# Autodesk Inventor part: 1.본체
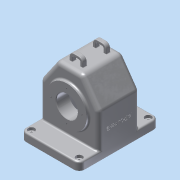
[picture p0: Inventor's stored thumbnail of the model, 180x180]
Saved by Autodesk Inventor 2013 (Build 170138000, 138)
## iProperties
Created: 2016-12
Part Number: 1.본체
Material: 알루미늄 6061
Document SubType Name: Modeling
Designer: Administrator
Density: 2.71 g/cm^3
Mass: 1067.35 g
Surface Area: 1137.96 cm^2
Volume: 393.856 cm^3
Author: Administrator
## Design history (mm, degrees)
sketch "스케치1"
  geometry: L1 (-55, 80)-(-55, 0); L2 (-55, 0)-(55, 0); L3 (55, 0)-(55, 80); L4 (55, 80)-(23.491, 125); L5 (23.491, 125)-(-23.491, 125); L6 (-23.491, 125)-(-55, 80); 3 further points
  constraints: 12 end point, 2 midpoint, 2 parallel, 1 coincident, 1 perpendicular, 1 vertical, 1 vertical alignment
  dimensions: "d0" = 110 distance of L1.end L2.end; "d2" = 80 distance of L2.end L3.end; "d3" = 80 distance of L1.start L1.end; "d4" = 125 distance between parallel lines of L2 L5; "d5" = 35 deg angle of L6 L1; "d6" = 35 deg angle of L4 L3 (derived)
extrude "돌출1" new body sketch "스케치1" stored distance "d7" = 77; taper "d8" = 0 deg
feature "쉘1" dims "d9" = 5
sketch "스케치2"
  geometry: L1 (78.424, 33.5)-(0, 33.5) reference; L2 (80, 38.5)-(0, 38.5) reference; L3 (0, -33.5)-(78.424, -33.5) reference; L4 (0, -38.5)-(80, -38.5) reference; L5 (65, 33.5)-(65, -33.5); L6 (120, 33.5)-(78.424, 33.5) reference; L7 (125, 38.5)-(80, 38.5) reference; L8 (65, 33.5)-(65, 19.5); L9 (65, 19.5)-(92, 19.5); L10 (92, 19.5)-(106, 33.5); 1 further point
  constraints: 8 end point, 4 point on line, 2 perpendicular
  dimensions: "d10" = 65 distance from line of L5 point (0, 0); "d12" = 14 distance between parallel lines of L1 L9; "d13" = 54 diameter of L9.end L5; "d14" = 45 deg angle of L10 L9
revolve "회전1" sketch "스케치2" stored, may be unused: angle "d15" = 90 deg
sketch "스케치3"
  geometry: L1 (-55, 0)-(55, 0) reference; C1 r 37.5 at (0, 65); 2 further points
  constraints: 1 centre point, 1 midpoint, 1 vertical alignment
  dimensions: "d16" = 65 distance of point (0, 0) C1.centre; "d17" = 75 diameter of C1
extrude "돌출2" join sketch "스케치3" distance "d18" = 5; taper "d19" = 0 deg
sketch "스케치4"
  geometry: L1 (-55, 0)-(55, 0) reference; C1 r 31 at (0, 65); 2 further points
  constraints: 1 centre point, 1 midpoint, 1 vertical alignment
  dimensions: "d20" = 65 distance of point (0, 0) C1.centre; "d21" = 62 diameter of C1
extrude "돌출3" join sketch "스케치4" distance "d22" = 10; taper "d23" = 0 deg
hole "구멍1" diameter "d26" = 40; stored, may be unused: countersink angle "d30" = 90 deg, drill point angle "d32" = 118 deg; dims "d24" = 10, "d25" = 10, "d27" = 6, "d28" = 4, "d29" = 2, "d31" = 8
sketch "스케치5" dims "d33" = 58
  geometry: C1 r 20 at (0, 0) reference; 3 further points
  constraints: 2 vertical alignment, 1 coincident, 2 other
hole "구멍2" sketch "스케치5" at (0, 29) diameter "d35" = 2.459; stored, may be unused: countersink angle "d39" = 90 deg, drill point angle "d41" = 118 deg; dims "d36" = 6, "d37" = 4, "d38" = 2, "d40" = 8
sketch "스케치6" dims "d45" = 52
  geometry: C1 r 20 at (0, 0) reference; 3 further points
  constraints: 2 vertical alignment, 1 coincident, 2 other
hole "구멍3" sketch "스케치6" at (0, 26) diameter "d47" = 2.459; stored, may be unused: countersink angle "d51" = 90 deg, drill point angle "d53" = 118 deg; dims "d48" = 6, "d49" = 4, "d50" = 2, "d52" = 8
chamfer "모따기1" distance "d57" = 1; stored, may be unused: second distance "d58" = 2, angle "d59" = 45 deg
sketch "스케치7"
  geometry: L1 (110, -77)-(110, 0) reference; L2 (105, -5)-(105, -72) reference; L3 (105, -72)-(5, -72) reference; L4 (5, -72)-(5, -5) reference; L5 (5, -5)-(105, -5) reference; L6 (110, -77)-(110, 0) reference; L7 (0, 0)-(110, 0) reference; L8 (0, -77)-(0, 0) reference; L9 (110, -77)-(0, -77) reference; L10 (0, 36.5)-(110, 36.5); L11 (110, 36.5)-(110, -113.5); L12 (110, -113.5)-(0, -113.5); L13 (0, -113.5)-(0, 36.5); L14 (0, 36.5)-(110, -113.5); 2 further points
  constraints: 10 end point, 2 parallel, 1 coincident, 1 horizontal, 1 midpoint, 1 perpendicular
  dimensions: "d60" = 150 distance of L12.end L10.start; "d62" = 110 distance of L11.end L12.end
extrude "돌출4" join sketch "스케치7" distance "d63" = 15; taper "d64" = 0 deg
fillet "모깎기1" dims "d65" = 10
sketch "스케치8"
  geometry: L1 (10, -36.5)-(100, -36.5) reference; L2 (110, -26.5)-(110, 0) reference; L3 (0, 0)-(110, 0) reference; L4 (0, 0)-(0, -26.5) reference; L5 (0, 103.5)-(0, 77) reference; L6 (110, 77)-(0, 77) reference; L7 (110, 77)-(110, 103.5) reference; L8 (100, 113.5)-(10, 113.5) reference; A1 r 10 centre (10, -26.5) between (0, -26.5) and (10, -36.5) reference; A2 r 10 centre (100, -26.5) between (100, -36.5) and (110, -26.5) reference; A3 r 10 centre (10, 103.5) between (10, 113.5) and (0, 103.5) reference; A4 r 10 centre (100, 103.5) between (110, 103.5) and (100, 113.5) reference; 1 further point
hole "구멍4" sketch "스케치8" at (10, -26.5), (100, -26.5), (100, 103.5), (10, 103.5) diameter "d66" = 5; stored, may be unused: countersink angle "d70" = 90 deg, drill point angle "d72" = 0 deg; dims "d67" = 6, "d68" = 12, "d69" = 5, "d71" = 8
fillet "모깎기2" dims "d73" = 10
fillet "모깎기3" dims "d74" = 8
node "작업 평면1"
sketch "스케치9"
  geometry: L1 (-18.285, 125)-(18.285, 125) reference; L2 (-7.5, 125)-(-7.5, 135); L3 (-7.5, 135)-(7.5, 135); L4 (7.5, 135)-(7.5, 125); L5 (-12.5, 125)-(-12.5, 140); L6 (-12.5, 140)-(12.5, 140); L7 (12.5, 140)-(12.5, 125); L8 (50, 0)-(-50, 0) reference; 3 further points
  constraints: 12 end point, 5 perpendicular, 4 point on line, 2 midpoint, 2 vertical alignment, 1 parallel
  dimensions: "d76" = 25 distance of L5.end L6.end; "d78" = 15 distance of L2.end L3.end; "d79" = 140 distance between parallel lines of L6 L8; "d80" = 5 distance between parallel lines of L3 L6
extrude "돌출5" join sketch "스케치9" distance "d81" = 8; taper "d82" = 0 deg
fillet "모깎기4" dims "d83" = 8
fillet "모깎기5" dims "d84" = 3
fillet "모깎기6" dims "d85" = 1
fillet "모깎기7" dims "d86" = 1
fillet "모깎기8" dims "d87" = 1
fillet "모깎기9" dims "d88" = 3
fillet "모깎기10" dims "d89" = 3
fillet "모깎기11" dims "d90" = 3
fillet "모깎기12" dims "d91" = 3
fillet "모깎기13" dims "d92" = 5
fillet "모깎기14" dims "d93" = 3
sketch "스케치10"
  geometry: L1 (26.5, 76.847)-(26.5, 18) reference; L2 (130, 0)-(0, 0) reference; 2 further points
  constraints: 1 other
  dimensions: "d94" = 38.5 distance from line of point (65, 45) L1; "d95" = 45 distance from line of point (65, 45) L2
feature "엠보싱1" sketch "스케치10" dims "d96" = 0.5, "d97" = 0
node "솔리드1"
pattern_circular "원형 패턴1" dims angle "d43" = 360 deg
pattern_circular "원형 패턴2" dims angle "d55" = 360 deg
mirror "대칭1"
node "투영된 루프1"
node "투영된 루프2"
node "투영된 루프3"
other parameters: "d75" = -18
